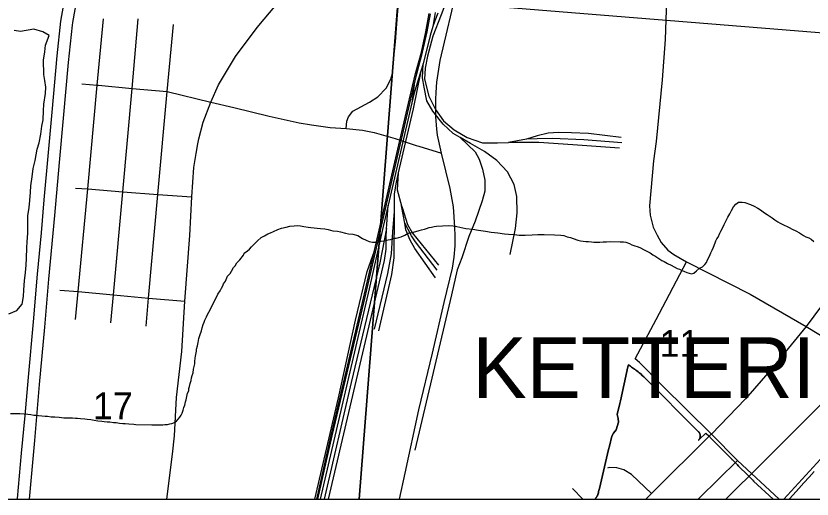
# Model space of a CAD drawing. Extents: x 0 to 34, y 0 to 22.
# Drawn here: x 4.199 to 5.442, y 14.1 to 14.854 of the extents above; entities that cross this region are included whole.
import ezdxf

# ---------------------------------------------------------------- set-up
doc = ezdxf.new("R2010")
doc.units = 0
for name, color, linetype in [('Default', 7, 'Continuous'), ('GM_X_City_Street', 7, 'Continuous'), ('GM_X_Corporation_Text', 7, 'Continuous'), ('GM_X_County_Road', 7, 'Continuous'), ('GM_X_Interstate_Route', 7, 'Continuous'), ('GM_X_Minor_Lake', 7, 'Continuous'), ('GM_X_Minor_River', 7, 'Continuous'), ('GM_X_Rail_Line', 7, 'Continuous'), ('GM_X_Section', 7, 'Continuous'), ('GM_X_Section_Text', 7, 'Continuous'), ('GM_X_State_Route', 7, 'Continuous'), ('GM_X_Township_Road', 7, 'Continuous'), ('SC_Shading3', 7, 'Continuous'), ('SH_Data', 7, 'Continuous')]:
    doc.layers.add(name, color=color, linetype=linetype)

msp = doc.modelspace()

# ---------------------------------------------------------------- linework, layer by layer
at = {"layer": 'Default'}
for points in [[(3.9705, 14.1), (4.7349, 14.1), (4.7957, 14.8813), (4.1906, 14.9321), (4.0525, 14.6548), (3.9958, 14.4577), (3.9463, 14.3814), (3.9481, 14.3196)], [(4.7349, 14.1), (5.7681, 14.1), (5.8197, 14.7981), (4.7957, 14.8813)], [(5.103, 14.1), (5.3811, 14.1), (5.3501, 14.1279), (5.3497, 14.1283), (5.3498, 14.1284), (5.3498, 14.1284), (5.35, 14.1286), (5.3501, 14.1287), (5.35, 14.1288), (5.3496, 14.1291), (5.3456, 14.133), (5.3456, 14.133), (5.3412, 14.1373), (5.327, 14.1516), (5.327, 14.1516), (5.3269, 14.1517), (5.3269, 14.1517), (5.3268, 14.1517), (5.3268, 14.1518), (5.3268, 14.1518), (5.3268, 14.1518), (5.3267, 14.1519), (5.3267, 14.1519), (5.3266, 14.152), (5.3266, 14.152), (5.3266, 14.152), (5.3266, 14.152), (5.3265, 14.1521), (5.3265, 14.1521), (5.325, 14.1536), (5.3214, 14.1572), (5.3183, 14.1603), (5.3168, 14.1619), (5.3168, 14.1619), (5.3167, 14.1619), (5.3167, 14.1619), (5.3166, 14.162), (5.3166, 14.162), (5.3166, 14.1621), (5.3166, 14.1621), (5.3165, 14.1621), (5.3165, 14.1621), (5.3164, 14.1622), (5.3164, 14.1622), (5.3164, 14.1623), (5.3163, 14.1623), (5.3163, 14.1623), (5.3163, 14.1623), (5.3016, 14.1771), (5.3016, 14.1771), (5.2847, 14.194), (5.2847, 14.194), (5.2803, 14.1985), (5.2802, 14.1985), (5.2762, 14.2026), (5.2758, 14.203), (5.2659, 14.1933), (5.2646, 14.192), (5.2645, 14.1919), (5.2645, 14.192), (5.2646, 14.192), (5.2647, 14.1921), (5.2648, 14.1922), (5.265, 14.1924), (5.2651, 14.1927), (5.2653, 14.1929), (5.2654, 14.1931), (5.2656, 14.1933), (5.2657, 14.1934), (5.2658, 14.1936), (5.2659, 14.1939), (5.2661, 14.1941), (5.2662, 14.1943), (5.2663, 14.1945), (5.2664, 14.1948), (5.2665, 14.195), (5.2666, 14.1953), (5.2667, 14.1955), (5.2668, 14.196), (5.2669, 14.1964), (5.267, 14.1969), (5.2671, 14.1975), (5.2671, 14.198), (5.2671, 14.1984), (5.2671, 14.1989), (5.2671, 14.1994), (5.2671, 14.1997), (5.267, 14.2001), (5.2669, 14.2004), (5.2669, 14.2008), (5.2667, 14.2012), (5.2666, 14.2016), (5.2665, 14.202), (5.2663, 14.2024), (5.2661, 14.2028), (5.2659, 14.2032), (5.2656, 14.2036), (5.2654, 14.2039), (5.2652, 14.2043), (5.2649, 14.2045), (5.2647, 14.2049), (5.2644, 14.2052), (5.1798, 14.29), (5.1789, 14.2909), (5.1767, 14.2931), (5.1742, 14.2953), (5.172, 14.2972), (5.17, 14.2987), (5.1684, 14.3), (5.1667, 14.3012), (5.1656, 14.302), (5.1645, 14.3028), (5.163, 14.3039), (5.1615, 14.3049), (5.1598, 14.3061), (5.1581, 14.3074), (5.1567, 14.3083), (5.1554, 14.3093), (5.1539, 14.3064), (5.1428, 14.2531), (5.1424, 14.2514), (5.1418, 14.2492), (5.1375, 14.2319), (5.1386, 14.2276), (5.1388, 14.226), (5.1397, 14.2202), (5.136, 14.2079), (5.1316, 14.2028), (5.1291, 14.198), (5.1254, 14.1824), (5.1242, 14.1775), (5.1097, 14.1164), (5.1086, 14.1119), (5.1086, 14.1116), (5.1085, 14.1112), (5.1084, 14.1108), (5.1084, 14.1105), (5.1083, 14.1101), (5.1082, 14.1098), (5.1081, 14.1094), (5.108, 14.1091), (5.1079, 14.1087), (5.1078, 14.1083), (5.1077, 14.1079), (5.1075, 14.1076), (5.1074, 14.1072), (5.1072, 14.1068), (5.1071, 14.1064), (5.1069, 14.106), (5.1067, 14.1056), (5.1066, 14.1053), (5.1064, 14.1049), (5.1062, 14.1045), (5.106, 14.1042), (5.1058, 14.1038), (5.1056, 14.1035), (5.1054, 14.1031), (5.1051, 14.1028), (5.1049, 14.1024), (5.1046, 14.1021), (5.1044, 14.1017), (5.1042, 14.1014), (5.1039, 14.1011), (5.1036, 14.1008), (5.1034, 14.1005), (5.1031, 14.1002)]]:
    msp.add_lwpolyline(points, close=True, dxfattribs=at)
at = {"layer": 'GM_X_City_Street'}
msp.add_line((5.0679, 14.1166), (5.0838, 14.1), dxfattribs=at)
for points in [[(4.7877, 14.7751), (4.7915, 14.8137), (4.795, 14.8556), (4.8014, 14.9307), (4.8064, 14.9848), (4.8088, 15.0142), (4.8154, 15.0879), (4.8165, 15.1025)], [(4.5036, 14.7192), (4.5157, 14.7466), (4.542, 14.7907), (4.5756, 14.8358), (4.6361, 14.9083), (4.67, 14.9564), (4.6934, 14.9962)], [(5.2146, 14.8789), (5.2126, 14.8172), (5.2077, 14.7541), (5.1981, 14.658), (5.1943, 14.628), (5.1877, 14.5576), (5.1889, 14.5431), (5.1938, 14.5246), (5.1999, 14.5119), (5.2062, 14.5004), (5.2164, 14.4886), (5.226, 14.4817), (5.2454, 14.4704), (5.345, 14.4199), (5.4323, 14.3694), (5.5063, 14.3244), (5.5711, 14.2911)], [(4.2926, 14.3805), (4.2966, 14.424), (4.3115, 14.5844), (4.3261, 14.7462), (4.3358, 14.8495)], [(4.3476, 14.3749), (4.3515, 14.419), (4.3661, 14.5796), (4.3809, 14.7406), (4.3903, 14.8496)], [(4.4024, 14.3698), (4.4062, 14.4138), (4.4208, 14.5751), (4.4355, 14.7359), (4.4451, 14.8404)], [(5.7437, 14.8064), (5.7235, 14.7837), (5.7022, 14.7545), (5.6809, 14.7225), (5.6658, 14.6992), (5.6539, 14.6703), (5.6445, 14.6401), (5.6328, 14.6129), (5.6182, 14.5852), (5.6033, 14.5624), (5.5909, 14.5467), (5.5775, 14.5326), (5.5598, 14.5157), (5.5197, 14.48), (5.4967, 14.4551), (5.4802, 14.434), (5.4323, 14.3694), (5.3764, 14.3005), (5.3376, 14.2566), (5.2844, 14.2013), (5.2837, 14.2006)], [(4.7146, 14.6782), (4.7156, 14.6898), (4.7181, 14.6965), (4.725, 14.7054), (4.7509, 14.7196), (4.7641, 14.7275), (4.7771, 14.7412), (4.7845, 14.7555), (4.7867, 14.7641), (4.7876, 14.7741), (4.7877, 14.7751)], [(4.3024, 14.7481), (4.3261, 14.7462), (4.3281, 14.746)], [(4.3281, 14.746), (4.3809, 14.7406), (4.4355, 14.7359), (4.5036, 14.7192)], [(4.485, 14.6622), (4.4916, 14.6881), (4.5036, 14.7192)], [(4.5036, 14.7192), (4.5392, 14.711), (4.5946, 14.6976), (4.6413, 14.6874), (4.6606, 14.6842), (4.6898, 14.6801), (4.7146, 14.6782), (4.7401, 14.6756), (4.7582, 14.6723), (4.7913, 14.6628), (4.8192, 14.6534), (4.824, 14.6519)], [(4.4349, 14.1), (4.4437, 14.1703), (4.4469, 14.1987), (4.45, 14.2586), (4.4581, 14.3301), (4.4632, 14.409), (4.4705, 14.5114), (4.4738, 14.5719), (4.477, 14.6175), (4.4804, 14.6391), (4.4831, 14.6545), (4.485, 14.6622)], [(4.824, 14.6519), (4.8278, 14.6506), (4.8636, 14.6398)], [(4.2923, 14.5854), (4.3115, 14.5844), (4.3661, 14.5796), (4.4208, 14.5751), (4.4738, 14.5719)], [(5.2844, 14.2013), (5.2079, 14.2775), (5.1725, 14.3134), (5.1656, 14.319), (5.1981, 14.38), (5.2454, 14.4704)], [(4.268, 14.4262), (4.2966, 14.424), (4.3515, 14.419), (4.4062, 14.4138), (4.4632, 14.409)], [(5.2837, 14.2006), (5.1909, 14.1089), (5.182, 14.1)], [(5.3901, 14.1), (5.3252, 14.1601), (5.2844, 14.2013)], [(5.1909, 14.1089), (5.1596, 14.1385), (5.1479, 14.1457), (5.137, 14.149), (5.1252, 14.1492), (5.1222, 14.1485)], [(5.264, 14.1), (5.2659, 14.1019), (5.3252, 14.1601)]]:
    msp.add_lwpolyline(points, dxfattribs=at)
at = {"layer": 'GM_X_County_Road'}
msp.add_lwpolyline([(5.3977, 14.1), (5.4663, 14.1746)], dxfattribs=at)
at = {"layer": 'GM_X_Interstate_Route'}
for points in [[(4.2876, 14.8397), (4.288, 14.8437), (4.2943, 14.8792), (4.3009, 14.909), (4.3123, 14.9437), (4.3213, 14.9665), (4.3362, 14.997), (4.3383, 15.0004)], [(4.2016, 14.1), (4.2017, 14.1009), (4.2081, 14.1716), (4.2136, 14.2302), (4.2188, 14.2904), (4.2266, 14.3766), (4.2331, 14.4509), (4.2394, 14.5154), (4.2437, 14.5669), (4.2499, 14.6353), (4.256, 14.7038), (4.2637, 14.7919), (4.2695, 14.8457), (4.2734, 14.8691)], [(4.2204, 14.1), (4.2287, 14.1914), (4.2362, 14.2789), (4.2445, 14.3681), (4.2509, 14.4434), (4.2603, 14.5425), (4.2676, 14.6254), (4.2737, 14.6945), (4.2816, 14.7814), (4.2876, 14.8397)]]:
    msp.add_lwpolyline(points, dxfattribs=at)
at = {"layer": 'GM_X_Minor_Lake'}
for points in [[(4.2272, 14.8335), (4.2067, 14.8297), (4.1968, 14.831)], [(4.217, 14.5016), (4.218, 14.5149), (4.2179, 14.5305), (4.2181, 14.5419), (4.2199, 14.5552), (4.2213, 14.5662), (4.2223, 14.5791), (4.2228, 14.5886), (4.2246, 14.6027), (4.2264, 14.616), (4.2293, 14.6284), (4.2327, 14.6463), (4.2355, 14.6561), (4.2381, 14.6694), (4.2398, 14.6819), (4.2419, 14.6921), (4.2422, 14.7058), (4.2432, 14.7164), (4.2454, 14.7331), (4.2459, 14.7426), (4.2443, 14.7533), (4.2429, 14.7628), (4.2426, 14.7849), (4.2447, 14.7978), (4.2457, 14.8084), (4.2513, 14.8235), (4.2412, 14.829), (4.2272, 14.8335)], [(4.1886, 14.3892), (4.2008, 14.3943), (4.209, 14.4044), (4.2115, 14.4162), (4.2117, 14.4268), (4.2127, 14.4405), (4.2145, 14.4538), (4.2155, 14.4648), (4.2161, 14.4762), (4.2164, 14.4921), (4.217, 14.5016)]]:
    msp.add_lwpolyline(points, dxfattribs=at)
at = {"layer": 'GM_X_Minor_River'}
for points in [[(4.7928, 14.5073), (4.797, 14.5084), (4.8004, 14.5094), (4.8062, 14.512), (4.8116, 14.5149), (4.8196, 14.5166), (4.8284, 14.519), (4.8322, 14.5201), (4.8368, 14.5211), (4.8399, 14.5221), (4.8441, 14.5236), (4.8476, 14.5246), (4.8518, 14.5253), (4.8556, 14.5259), (4.8647, 14.5265), (4.8746, 14.527), (4.8815, 14.5264), (4.8871, 14.5252), (4.9015, 14.5225), (4.9121, 14.5211), (4.9212, 14.5197), (4.9318, 14.518), (4.9409, 14.5166), (4.9515, 14.5156), (4.9618, 14.5138), (4.9678, 14.5133), (4.9773, 14.513), (4.9845, 14.5121), (4.9937, 14.5119), (5.0051, 14.5123), (5.0139, 14.5129), (5.0237, 14.513), (5.0397, 14.5126), (5.0496, 14.512), (5.0541, 14.5111), (5.0594, 14.5091), (5.0647, 14.5082), (5.0688, 14.5069), (5.076, 14.5041), (5.0805, 14.5028), (5.0885, 14.5019), (5.0927, 14.5018), (5.0972, 14.5013), (5.101, 14.5008), (5.1041, 14.5007), (5.1102, 14.501), (5.1155, 14.5016), (5.1208, 14.5015), (5.1277, 14.502), (5.1421, 14.5017), (5.1471, 14.5016), (5.1508, 14.5011), (5.1569, 14.4987), (5.1606, 14.497), (5.1648, 14.495), (5.1689, 14.4942), (5.1727, 14.4926), (5.1795, 14.489), (5.1828, 14.4874), (5.1888, 14.4842), (5.1933, 14.481), (5.1963, 14.4794), (5.2008, 14.4763), (5.2042, 14.4743), (5.2072, 14.4723), (5.2106, 14.4707), (5.2162, 14.4675), (5.2215, 14.4651), (5.2312, 14.4599), (5.2346, 14.4587), (5.2384, 14.4567), (5.2414, 14.4555), (5.2459, 14.4538), (5.2497, 14.4526), (5.2535, 14.4517), (5.2569, 14.4524), (5.2615, 14.4561), (5.2658, 14.4606), (5.2705, 14.4624), (5.274, 14.4661), (5.2771, 14.469), (5.2783, 14.4732), (5.2815, 14.4792), (5.2835, 14.4845), (5.2855, 14.4886), (5.2876, 14.4931), (5.2904, 14.4999), (5.2912, 14.5029), (5.2932, 14.5059), (5.2948, 14.5089), (5.2976, 14.5149), (5.2992, 14.5183), (5.3016, 14.5228), (5.3044, 14.5284), (5.31, 14.5397), (5.3132, 14.5453), (5.316, 14.5506), (5.3192, 14.5562), (5.3227, 14.5603), (5.3269, 14.5636), (5.3327, 14.5635)], [(5.3327, 14.5635), (5.3368, 14.563), (5.3455, 14.5597), (5.3511, 14.5573), (5.3568, 14.5541), (5.3609, 14.5514), (5.3654, 14.5482), (5.3687, 14.5459), (5.3717, 14.5443), (5.3762, 14.5411), (5.3792, 14.5387), (5.3837, 14.5356), (5.3882, 14.5328), (5.3919, 14.5304), (5.3949, 14.5288), (5.3979, 14.5276), (5.4025, 14.5256), (5.4058, 14.524), (5.4107, 14.5212), (5.416, 14.5184), (5.422, 14.5156), (5.428, 14.5113), (5.4317, 14.5093), (5.4366, 14.5076), (5.44, 14.5057), (5.4441, 14.5021)], [(4.4468, 14.2197), (4.4499, 14.2215), (4.4527, 14.2248), (4.4554, 14.2278), (4.4574, 14.2312), (4.4586, 14.2342), (4.4602, 14.2387), (4.4615, 14.2429), (4.4627, 14.2467), (4.464, 14.2516), (4.4648, 14.255), (4.4661, 14.2599), (4.4673, 14.2652), (4.469, 14.2689), (4.4694, 14.2724), (4.4703, 14.2758), (4.4715, 14.2803), (4.4728, 14.2852), (4.4736, 14.2894), (4.4745, 14.2928), (4.4757, 14.2969), (4.4766, 14.3026), (4.4784, 14.3113), (4.4788, 14.3147), (4.4793, 14.32), (4.4798, 14.3231), (4.4811, 14.3306), (4.4812, 14.3341), (4.4825, 14.339), (4.4837, 14.3443), (4.485, 14.3507), (4.4867, 14.3571), (4.4888, 14.3628), (4.49, 14.3673), (4.4917, 14.3726), (4.4929, 14.376), (4.4941, 14.379), (4.4969, 14.3846), (4.4985, 14.388), (4.5025, 14.3955), (4.5049, 14.4012), (4.5081, 14.4068), (4.5145, 14.4196), (4.5181, 14.4252), (4.5201, 14.4293), (4.522, 14.4327), (4.5233, 14.4357), (4.5264, 14.4402), (4.5293, 14.4477), (4.5335, 14.4518), (4.5359, 14.4559), (4.5387, 14.4612), (4.5415, 14.4642), (4.5439, 14.4687), (4.5489, 14.4735), (4.5544, 14.4806), (4.5556, 14.484), (4.5607, 14.4873), (4.5638, 14.4902), (4.5669, 14.4936), (4.5712, 14.498), (4.5763, 14.5032), (4.5821, 14.508), (4.5875, 14.5109), (4.5925, 14.5138), (4.5967, 14.5156), (4.6013, 14.5178), (4.6079, 14.5207), (4.614, 14.5228), (4.6209, 14.5246), (4.627, 14.5259), (4.6335, 14.5265), (4.6392, 14.5268), (4.6434, 14.5263), (4.6487, 14.5254), (4.6555, 14.5241), (4.6593, 14.5236), (4.6646, 14.5235), (4.6692, 14.523), (4.6745, 14.5221), (4.6813, 14.5215), (4.6866, 14.5206), (4.6938, 14.5186), (4.701, 14.518), (4.7059, 14.5171), (4.7138, 14.515), (4.7184, 14.5141), (4.7252, 14.5132), (4.7328, 14.5115), (4.7403, 14.5064), (4.7459, 14.5039), (4.7508, 14.5019), (4.7557, 14.501), (4.7603, 14.5009), (4.7645, 14.5016), (4.7694, 14.5026), (4.774, 14.5032), (4.7801, 14.5046), (4.784, 14.5053), (4.7889, 14.5071), (4.7928, 14.5073)], [(4.1912, 14.2336), (4.2015, 14.2334), (4.2057, 14.2333), (4.2125, 14.2331), (4.2182, 14.2326), (4.2228, 14.2321), (4.2273, 14.2312), (4.2311, 14.2311), (4.2349, 14.2306), (4.2398, 14.2298), (4.2451, 14.2296), (4.2485, 14.2292), (4.2542, 14.2286), (4.2603, 14.2281), (4.2668, 14.2276), (4.274, 14.227), (4.2793, 14.2269), (4.2842, 14.2267), (4.2877, 14.2267), (4.2926, 14.2262), (4.2956, 14.2261), (4.3002, 14.2256), (4.307, 14.225), (4.3104, 14.2246), (4.3165, 14.224), (4.3214, 14.2232), (4.3271, 14.2223), (4.3332, 14.2217), (4.337, 14.2213), (4.3419, 14.2207), (4.3461, 14.2203), (4.3518, 14.2197), (4.3559, 14.2193), (4.3612, 14.2187), (4.3662, 14.2182), (4.37, 14.2178), (4.3757, 14.2172), (4.3836, 14.217), (4.3867, 14.2166), (4.4114, 14.216), (4.4163, 14.2159), (4.4216, 14.2157), (4.4247, 14.216), (4.4285, 14.2159), (4.4315, 14.2162), (4.4357, 14.2165), (4.4395, 14.2172), (4.4426, 14.2182), (4.4468, 14.2197)]]:
    msp.add_lwpolyline(points, dxfattribs=at)
at = {"layer": 'GM_X_Rail_Line'}
for p, q in [((4.8535, 14.8594), (4.8501, 14.8374)), ((4.8208, 14.7464), (4.8169, 14.7182)), ((4.8169, 14.7182), (4.7802, 14.5589)), ((4.9959, 14.6618), (4.968, 14.6567)), ((4.806, 14.5308), (4.8012, 14.5577))]:
    msp.add_line(p, q, dxfattribs=at)
for points in [[(5.307, 14.1), (5.3631, 14.1553), (5.4764, 14.2689), (5.5203, 14.3207), (5.5845, 14.4093), (5.6343, 14.4994), (5.6716, 14.6011), (5.73, 14.7768), (5.8229, 15.1019), (5.9915, 15.7798), (6.009, 15.8879), (6.0182, 15.9378), (6.0296, 15.9699), (6.0498, 16.001), (6.1077, 16.0613), (6.165, 16.1203), (6.2534, 16.207)], [(4.8813, 14.9215), (4.8726, 14.8821), (4.8628, 14.8558), (4.85, 14.8226), (4.8414, 14.7911), (4.8378, 14.7723), (4.8371, 14.7555), (4.8437, 14.7289), (4.8542, 14.7079), (4.8667, 14.6901), (4.8832, 14.676), (4.9032, 14.6641), (4.9272, 14.6562), (4.9509, 14.6562), (4.968, 14.6567)], [(4.6687, 14.1), (4.691, 14.1992), (4.7403, 14.4069), (4.7954, 14.646), (4.8137, 14.7247), (4.823, 14.7639), (4.832, 14.7977), (4.839, 14.8294), (4.8441, 14.8577)], [(4.6706, 14.1), (4.6929, 14.1987), (4.7422, 14.4064), (4.7973, 14.6455), (4.8156, 14.7243), (4.8248, 14.7634), (4.8339, 14.7973), (4.8409, 14.829), (4.846, 14.8574)], [(4.8577, 14.8584), (4.853, 14.8464), (4.8501, 14.8374)], [(4.8501, 14.8374), (4.8456, 14.8234), (4.8349, 14.7794), (4.8313, 14.7679)], [(4.8925, 14.6644), (4.8818, 14.6707), (4.8661, 14.6852), (4.85, 14.7056), (4.8407, 14.7213), (4.8361, 14.743), (4.8338, 14.7575), (4.8349, 14.7794)], [(4.8313, 14.7679), (4.819, 14.7089), (4.7973, 14.6161), (4.7958, 14.6092)], [(4.8313, 14.7679), (4.8201, 14.7321), (4.8169, 14.7182)], [(5.1439, 14.6645), (5.0926, 14.6704), (5.066, 14.6717), (5.0466, 14.672), (5.0298, 14.671), (5.0127, 14.6668), (4.9959, 14.6618)], [(4.8925, 14.6644), (4.9157, 14.6421), (4.9223, 14.6303), (4.9276, 14.6151), (4.9312, 14.5977), (4.9308, 14.5806), (4.9266, 14.5655), (4.916, 14.5339), (4.9062, 14.5096), (4.895, 14.4767), (4.8878, 14.4576), (4.8789, 14.4188), (4.8217, 14.1762)], [(4.9706, 14.4816), (4.9788, 14.5224), (4.9815, 14.5467), (4.9811, 14.5721), (4.9769, 14.5911), (4.9664, 14.6109), (4.9499, 14.6286), (4.9305, 14.6424), (4.9085, 14.6549), (4.8925, 14.6644)], [(5.1446, 14.6562), (5.0857, 14.6605), (5.0361, 14.6625), (5.0124, 14.6622), (4.9959, 14.6618)], [(4.968, 14.6567), (4.9775, 14.6569), (5.015, 14.6572), (5.0683, 14.6536), (5.1413, 14.648)], [(4.7958, 14.6092), (4.7921, 14.5921), (4.7895, 14.576), (4.7895, 14.549)], [(4.7958, 14.6092), (4.7941, 14.5826), (4.8012, 14.5577)], [(4.7802, 14.5589), (4.7724, 14.5254), (4.7507, 14.428), (4.6743, 14.1)], [(4.7778, 14.5224), (4.7779, 14.5283), (4.7802, 14.5589)], [(4.7895, 14.549), (4.7868, 14.5172), (4.7849, 14.4826), (4.7789, 14.4521), (4.7585, 14.3652)], [(4.7895, 14.549), (4.7891, 14.4767), (4.7855, 14.4507), (4.7651, 14.3626)], [(4.8012, 14.5577), (4.8019, 14.555), (4.8105, 14.5283), (4.8181, 14.5152), (4.8588, 14.4652)], [(4.7778, 14.5224), (4.7674, 14.4685), (4.7227, 14.2821), (4.6801, 14.1)], [(4.6871, 14.1), (4.7747, 14.4724), (4.7773, 14.4902), (4.7773, 14.507), (4.7778, 14.5224)], [(4.8539, 14.4451), (4.8217, 14.4909), (4.8144, 14.504), (4.8079, 14.5204), (4.806, 14.5308)], [(4.8565, 14.457), (4.8227, 14.5014), (4.8164, 14.5109), (4.806, 14.5308)], [(4.6657, 14.1), (4.7025, 14.2578), (4.7293, 14.3791), (4.7475, 14.4554), (4.7589, 14.4875)]]:
    msp.add_lwpolyline(points, dxfattribs=at)
at = {"layer": 'GM_X_Section'}
msp.add_lwpolyline([(4.8205, 15.1342), (5.8133, 15.0467), (5.8372, 15.0451), (5.8197, 14.7981), (4.7957, 14.8813)], close=True, dxfattribs=at)
at = {"layer": 'GM_X_State_Route'}
for points in [[(4.8551, 14.7344), (4.8562, 14.7504), (4.8615, 14.7842), (4.889, 14.9013)], [(4.8563, 14.6774), (4.8544, 14.6972), (4.8544, 14.724), (4.8551, 14.7344)], [(4.8636, 14.6398), (4.8572, 14.668), (4.8563, 14.6774)], [(4.7979, 14.1), (4.8066, 14.1407), (4.8282, 14.2394), (4.8493, 14.3275), (4.8678, 14.4069), (4.8804, 14.4601), (4.8831, 14.4773), (4.8845, 14.4952), (4.8848, 14.5106), (4.8843, 14.5243), (4.8823, 14.5562), (4.877, 14.5848), (4.8636, 14.6398)]]:
    msp.add_lwpolyline(points, dxfattribs=at)
at = {"layer": 'GM_X_Township_Road'}
msp.add_lwpolyline([(4.1134, 14.9203), (4.0327, 14.7508), (4.0134, 14.7065), (3.953, 14.5775), (3.9279, 14.5145), (3.9171, 14.4692), (3.8965, 14.2487), (3.9136, 14.1656), (3.9251, 14.1), (8.9, 14.1)], dxfattribs=at)
at = {"layer": 'SC_Shading3'}
msp.add_lwpolyline([(2.1, 14.1), (5.103, 14.1), (5.1031, 14.1002), (5.1034, 14.1005), (5.1036, 14.1008), (5.1039, 14.1011), (5.1042, 14.1014), (5.1044, 14.1017), (5.1046, 14.1021), (5.1049, 14.1024), (5.1051, 14.1028), (5.1054, 14.1031), (5.1056, 14.1035), (5.1058, 14.1038), (5.106, 14.1042), (5.1062, 14.1045), (5.1064, 14.1049), (5.1066, 14.1053), (5.1067, 14.1056), (5.1069, 14.106), (5.1071, 14.1064), (5.1072, 14.1068), (5.1074, 14.1072), (5.1075, 14.1076), (5.1077, 14.1079), (5.1078, 14.1083), (5.1079, 14.1087), (5.108, 14.1091), (5.1081, 14.1094), (5.1082, 14.1098), (5.1083, 14.1101), (5.1084, 14.1105), (5.1084, 14.1108), (5.1085, 14.1112), (5.1086, 14.1115), (5.1086, 14.1116), (5.1086, 14.1119), (5.1097, 14.1164), (5.1242, 14.1775), (5.1254, 14.1824), (5.1291, 14.198), (5.1316, 14.2028), (5.136, 14.2079), (5.1397, 14.2202), (5.1388, 14.226), (5.1386, 14.2276), (5.1375, 14.2319), (5.1418, 14.2492), (5.1424, 14.2514), (5.1428, 14.2531), (5.1539, 14.3064), (5.1554, 14.3093), (5.1567, 14.3083), (5.1581, 14.3074), (5.1598, 14.3061), (5.1615, 14.3049), (5.163, 14.3039), (5.1645, 14.3028), (5.1656, 14.302), (5.1667, 14.3012), (5.1684, 14.3), (5.17, 14.2987), (5.172, 14.2972), (5.1742, 14.2953), (5.1767, 14.2931), (5.1789, 14.2909), (5.1796, 14.2901), (5.1798, 14.29), (5.2644, 14.2052), (5.2647, 14.2049), (5.2649, 14.2045), (5.2652, 14.2043), (5.2654, 14.2039), (5.2656, 14.2036), (5.2659, 14.2032), (5.2661, 14.2028), (5.2663, 14.2024), (5.2665, 14.202), (5.2666, 14.2016), (5.2667, 14.2012), (5.2669, 14.2008), (5.2669, 14.2004), (5.267, 14.2001), (5.2671, 14.1997), (5.2671, 14.1994), (5.2671, 14.1989), (5.2671, 14.1984), (5.2671, 14.198), (5.2671, 14.1975), (5.267, 14.1969), (5.2669, 14.1964), (5.2668, 14.196), (5.2667, 14.1955), (5.2666, 14.1953), (5.2665, 14.195), (5.2664, 14.1948), (5.2663, 14.1945), (5.2662, 14.1943), (5.2661, 14.1941), (5.2659, 14.1939), (5.2658, 14.1936), (5.2657, 14.1934), (5.2656, 14.1933), (5.2654, 14.1931), (5.2653, 14.1929), (5.2651, 14.1927), (5.265, 14.1924), (5.2648, 14.1922), (5.2647, 14.1921), (5.2646, 14.192), (5.2645, 14.192), (5.2645, 14.1919), (5.2646, 14.192), (5.2659, 14.1933), (5.2758, 14.203), (5.2762, 14.2026), (5.2803, 14.1985), (5.2847, 14.194), (5.3016, 14.1771), (5.3016, 14.1771), (5.3163, 14.1623), (5.3163, 14.1623), (5.3163, 14.1623), (5.3164, 14.1623), (5.3164, 14.1622), (5.3164, 14.1622), (5.3165, 14.1621), (5.3165, 14.1621), (5.3166, 14.1621), (5.3166, 14.1621), (5.3166, 14.162), (5.3166, 14.162), (5.3167, 14.1619), (5.3167, 14.1619), (5.3168, 14.1619), (5.3168, 14.1619), (5.3183, 14.1603), (5.3214, 14.1572), (5.325, 14.1536), (5.3265, 14.1521), (5.3265, 14.1521), (5.3266, 14.152), (5.3266, 14.152), (5.3266, 14.152), (5.3266, 14.152), (5.3267, 14.1519), (5.3267, 14.1519), (5.3268, 14.1518), (5.3268, 14.1518), (5.3268, 14.1518), (5.3268, 14.1517), (5.3269, 14.1517), (5.3269, 14.1517), (5.327, 14.1516), (5.327, 14.1516), (5.3412, 14.1373), (5.3412, 14.1373), (5.3456, 14.133), (5.3456, 14.133), (5.3496, 14.1291), (5.35, 14.1288), (5.3501, 14.1287), (5.35, 14.1286), (5.3498, 14.1284), (5.3498, 14.1284), (5.3497, 14.1283), (5.3501, 14.1279), (5.3811, 14.1), (5.4059, 14.1), (5.4119, 14.1066), (5.421, 14.1166), (5.4287, 14.1251), (5.4371, 14.1344), (5.4448, 14.1428)], dxfattribs=at)
at = {"layer": 'SH_Data'}
msp.add_line((2.1, 14.1), (8.9, 14.1), dxfattribs=at)

# ---------------------------------------------------------------- texts
at = {"layer": 'GM_X_Corporation_Text'}
msp.add_text('KETTERING', height=0.0947, rotation=0, dxfattribs=at).set_placement((4.9117, 14.2579))
at = {"layer": 'GM_X_Section_Text'}
for s, p in [('11', (5.2037, 14.322)), ('17', (4.3195, 14.2246))]:
    msp.add_text(s, height=0.04186, rotation=0, dxfattribs=at).set_placement(p)

doc.saveas('drawing.dxf')
